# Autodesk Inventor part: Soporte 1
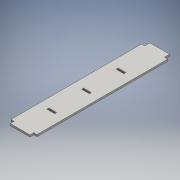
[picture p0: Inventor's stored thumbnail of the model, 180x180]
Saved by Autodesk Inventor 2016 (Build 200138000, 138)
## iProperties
Created: 2016-06
Part Number: Soporte 1
Material: Genérico
Document SubType Name: Modeling
Designer: adm
Density: 1 g/cm^3
Appearance: Valor por defecto
Author: adm
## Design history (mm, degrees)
sketch "Boceto1"
  geometry: L1 (40, 0)-(40, -200); L2 (0, -200)-(0, 0); L3 (5, 0)-(5, 8); L4 (5, 8)-(35, 8); L5 (35, 8)-(35, 0); L6 (35, -200)-(35, -206); L7 (35, -206)-(5, -206); L8 (5, -206)-(5, -200); L9 (40, -200)-(35, -200); L10 (5, -200)-(0, -200); L11 (0, 0)-(5, 0); L12 (35, 0)-(40, 0)
  constraints: 24 end point, 7 parallel, 2 horizontal, 2 perpendicular
  dimensions: "d0" = 200 distance of L1.start L1.end; "d1" = 40 distance of L2.end L1.start; "d2" = 30 distance of L3.end L4.end; "d3" = 5 distance between parallel lines of L2 L3; "d5" = 5 distance between parallel lines of L1 L6; "d6" = 30 distance of L6.end L7.end
extrude "Extrusión1" new body sketch "Boceto1" distance "d8" = 3; taper "d9" = 0 deg
sketch "Boceto3"
  geometry: L1 (14, -50)-(26, -50); L2 (26, -50)-(26, -53); L3 (26, -53)-(14, -53); L4 (14, -53)-(14, -50); L5 (5, 0)-(0, 0) reference; L6 (0, 0)-(0, -200) reference; L7 (14, -103)-(26, -103); L8 (26, -103)-(26, -106); L9 (26, -106)-(14, -106); L10 (14, -106)-(14, -103); L11 (14, -156)-(26, -156); L12 (26, -156)-(26, -159); L13 (26, -159)-(14, -159); L14 (14, -159)-(14, -156); 2 further points
  constraints: 24 end point, 6 parallel, 3 horizontal, 3 perpendicular, 2 midpoint, 1 vertical alignment
  dimensions: "d10" = 3 distance between parallel lines of L3 L1; "d11" = 12 distance between parallel lines of L2 L4; "d12" = 50 distance between parallel lines of L1 L5; "d13" = 14 distance between parallel lines of L6 L4; "d14" = 3 distance of L7.end L8.end; "d15" = 12 distance of L7.start L7.end; "d16" = 50 distance between parallel lines of L7 L3; "d17" = 3 distance of L11.end L12.end; "d18" = 12 distance of L11.start L11.end; "d19" = 14 distance between parallel lines of L6 L14; "d20" = 50 distance between parallel lines of L11 L9
extrude "Extrusión2" cut sketch "Boceto3" stored distance "d21" = 10; taper "d22" = 0 deg
node "Sólido1"
other parameters: "d4" = 8, "d7" = 6
